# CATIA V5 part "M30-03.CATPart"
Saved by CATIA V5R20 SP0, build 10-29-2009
Part number: M30-03
Revision: ANY
Definition: UNKNOWN
Nomenclature: M30-03
Source: Unknown
Bounding box of the stored display mesh (mm): x 0 to 63, y -25 to 25, z 0 to 25
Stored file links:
  C:\Users\Utente\Desktop\IO LAVORO\3D X SITO CF\X 3D SITO CF 27-09-2020\740T\740T-30\M30-03.CATPart
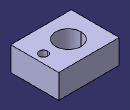
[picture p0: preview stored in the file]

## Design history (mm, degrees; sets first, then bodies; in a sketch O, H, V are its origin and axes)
Body1 "NONE" (main body)
  Solid1: solid without history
